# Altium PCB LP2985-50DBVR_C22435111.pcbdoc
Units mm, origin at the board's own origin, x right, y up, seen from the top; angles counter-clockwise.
Board outline 16.2 x 15.96 mm, 2 copper layers (Top Layer, Bottom Layer), stack 0 mm thick; 1 components, 0 nets, 5 pads, 0 vias.
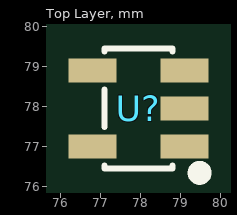
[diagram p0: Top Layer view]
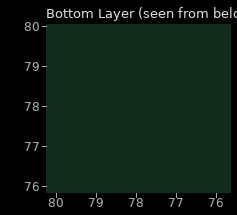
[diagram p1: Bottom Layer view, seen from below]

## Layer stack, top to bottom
Top Layer: signal copper (thickness not stored)
Bottom Layer: signal copper (thickness not stored)

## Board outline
86.05,69.85 69.85,69.85 69.85,85.811 86.05,85.811

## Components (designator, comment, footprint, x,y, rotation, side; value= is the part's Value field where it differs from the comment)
U? "LP2985-50DBVR" SOT-23-5_L3.0-W1.6-P0.95-LS2.8-BR 77.95,77.961 r0 top

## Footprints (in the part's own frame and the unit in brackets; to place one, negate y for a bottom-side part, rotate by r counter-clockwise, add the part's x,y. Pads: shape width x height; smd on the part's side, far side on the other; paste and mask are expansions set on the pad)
SOT-23-5_L3.0-W1.6-P0.95-LS2.8-BR [mm]
  rect 1.2x0.6 smd paste+0 mask+0.05: 1(1.15,-0.95) 2(1.15,0) 3(1.15,0.95) 4(-1.15,0.95) 5(-1.15,-0.95)
  silkscreen extent -0.85,-1.76 1.68,1.5

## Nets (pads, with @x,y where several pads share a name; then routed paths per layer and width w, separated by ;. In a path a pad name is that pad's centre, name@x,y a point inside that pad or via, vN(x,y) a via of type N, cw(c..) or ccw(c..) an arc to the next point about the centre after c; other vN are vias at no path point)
pads on no net: U?.1 U?.2 U?.3 U?.4 U?.5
